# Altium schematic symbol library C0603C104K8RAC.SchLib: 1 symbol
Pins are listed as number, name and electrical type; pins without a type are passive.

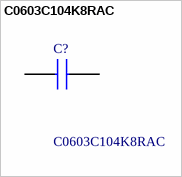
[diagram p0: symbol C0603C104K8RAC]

## C0603C104K8RAC
designator C?
Multilayer Ceramic Capacitors MLCC - SMD/SMT 10V 0.1uF X7R 0603 10%; Manufacturer_Name: KEMET; Geometry.Height: 0.95mm
footprint CAPC1608X95N
pins: 1, 2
